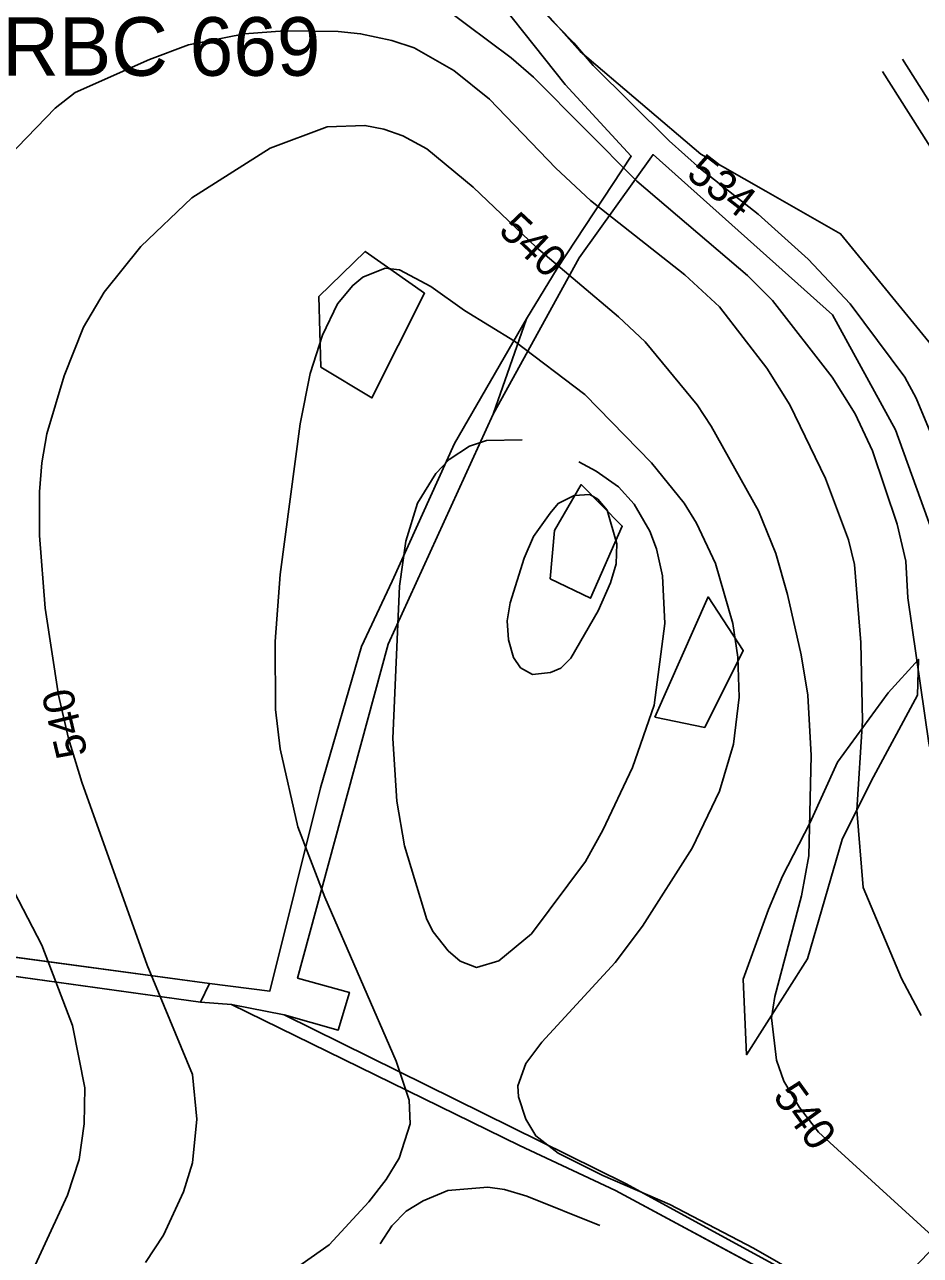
# Model space of a CAD drawing. Extents: x -709418 to -703832, y -1161719 to -1157826.
# Drawn here: x -708387.9 to -708158.7, y -1158300.7 to -1157985.6 of the extents above; entities that cross this region are included whole.
import ezdxf

# ---------------------------------------------------------------- set-up
doc = ezdxf.new("R2010")
doc.units = 0
for name, color, linetype in [('102_obvod PÚ', 7, 'Continuous'), ('103_hranice KÚ', 7, 'Continuous'), ('120_vrstevnice hlavní', 7, 'Continuous'), ('121_vrstevnice hlavní_popis', 7, 'Continuous'), ('122_vrstevnice základní', 7, 'Continuous'), ('124_vrstevnice doplňková', 7, 'Continuous'), ('206_TTP_KN', 7, 'Continuous'), ('210_ostatní plocha_KN', 7, 'Continuous'), ('501_vodní tok', 7, 'Continuous'), ('605_RBC_návrh_popis', 7, 'Continuous'), ('735_OP sítí TI', 7, 'Continuous')]:
    doc.layers.add(name, color=color, linetype=linetype)

msp = doc.modelspace()

# ---------------------------------------------------------------- linework, layer by layer
at = {"layer": '102_obvod PÚ'}
msp.add_lwpolyline([(-708273.66, -1157970.5), (-708249.53, -1158000.91), (-708232.65, -1158019.27), (-708251.62, -1158048.01), (-708259.43, -1158060.9), (-708267.99, -1158085.37), (-708245.93, -1158045.28), (-708227.05, -1158018.9), (-708181.16, -1158059.93), (-708164.98, -1158089.32), (-708147.17, -1158138.79)], dxfattribs=at)
at = {"layer": '103_hranice KÚ'}
msp.add_lwpolyline([(-708154.2, -1158069.65), (-708179.06, -1158039.17), (-708198.21, -1158028.27), (-708214.82, -1158018.74), (-708245.71, -1157992.5), (-708254.08, -1157983.08)], dxfattribs=at)
at = {"layer": '120_vrstevnice hlavní'}
for points in [[(-708195.48, -1158250.69), (-708196.76, -1158239.84), (-708195.91, -1158234.41), (-708189.05, -1158208.69), (-708187.19, -1158198.41), (-708186.62, -1158172.69), (-708187.48, -1158157.26), (-708189.19, -1158146.97), (-708192.62, -1158131.55), (-708195.62, -1158120.97), (-708200.05, -1158110.11), (-708212.19, -1158088.4), (-708215.76, -1158082.97), (-708229.05, -1158066.83), (-708235.91, -1158060.4), (-708256.91, -1158042.68), (-708273.05, -1158027.25), (-708284.91, -1158017.4), (-708291.05, -1158014.11), (-708295.91, -1158012.4), (-708300.77, -1158011.4), (-708310.48, -1158011.82), (-708325.06, -1158017.25), (-708345.06, -1158029.97), (-708358.11, -1158042.45), (-708367.48, -1158054.11), (-708372.77, -1158063.11), (-708377.77, -1158075.54), (-708382.2, -1158090.4), (-708383.49, -1158097.83), (-708384.06, -1158105.26), (-708384.06, -1158116.4), (-708382.63, -1158134.97), (-708379.2, -1158157.26), (-708376.63, -1158168.4), (-708373.2, -1158179.55), (-708356.48, -1158226.41), (-708344.91, -1158254.41), (-708343.77, -1158265.84), (-708344.91, -1158276.98), (-708347.2, -1158284.41), (-708352.34, -1158295.55), (-708356.91, -1158302.55)], [(-708133.62, -1158318.41), (-708155.62, -1158295.7), (-708184.76, -1158269.12), (-708189.62, -1158262.84), (-708193.62, -1158256.12), (-708195.48, -1158250.69)]]:
    msp.add_lwpolyline(points, dxfattribs=at)
at = {"layer": '122_vrstevnice základní'}
for points in [[(-708266.91, -1157970.11), (-708247.34, -1157990.25), (-708242.34, -1157996.11), (-708222.91, -1158015.4), (-708214.91, -1158022.54), (-708200.19, -1158034.11), (-708187.33, -1158045.68), (-708176.62, -1158057.11), (-708162.62, -1158075.83), (-708159.76, -1158081.26), (-708151.9, -1158100.11), (-708147.33, -1158116.11), (-708141.05, -1158148.4), (-708132.05, -1158173.55), (-708125.62, -1158187.26), (-708121.76, -1158194.12), (-708114.33, -1158203.55), (-708096.04, -1158222.98), (-708081.9, -1158235.12), (-708069.9, -1158243.12), (-708045.9, -1158254.98), (-708033.9, -1158261.84), (-708019.61, -1158271.41), (-708005.61, -1158282.55)], [(-708286.2, -1157976.97), (-708263.34, -1157994.11), (-708257.62, -1157999.11), (-708231.19, -1158025.68), (-708202.91, -1158049.83), (-708196.48, -1158056.26), (-708181.19, -1158075.83), (-708175.33, -1158085.26), (-708170.9, -1158094.69), (-708164.62, -1158113.54), (-708162.33, -1158122.97), (-708161.9, -1158132.4), (-708156.47, -1158169.55), (-708151.33, -1158193.55), (-708149.47, -1158196.98), (-708138.05, -1158220.98), (-708127.76, -1158238.12), (-708119.33, -1158250.69), (-708111.9, -1158260.12), (-708099.61, -1158272.69), (-708088.47, -1158285.27), (-708079.9, -1158297.84), (-708067.47, -1158319.84)], [(-708158.47, -1158239.26), (-708163.47, -1158229.83), (-708173.33, -1158206.55), (-708174.91, -1158186.69), (-708173.48, -1158163.83), (-708173.91, -1158143.83), (-708175.48, -1158123.83), (-708177.05, -1158117.54), (-708182.91, -1158101.83), (-708192.05, -1158082.97), (-708197.91, -1158073.54), (-708210.05, -1158057.83), (-708218.91, -1158049.68), (-708243.05, -1158030.68), (-708251.91, -1158022.4), (-708268.91, -1158004.68), (-708278.05, -1157997.4), (-708288.2, -1157991.54), (-708293.91, -1157989.68), (-708301.91, -1157987.97), (-708307.62, -1157987.39), (-708321.34, -1157987.25), (-708331.63, -1157987.97), (-708345.91, -1157990.82), (-708355.91, -1157994.54), (-708374.91, -1158002.97), (-708380.06, -1158006.97), (-708399.42, -1158026.97)], [(-708329.77, -1158311.98), (-708309.91, -1158297.98), (-708299.77, -1158286.98), (-708295.34, -1158281.27), (-708292.05, -1158275.84), (-708289.2, -1158266.98), (-708289.48, -1158260.98), (-708292.77, -1158250.98), (-708311.05, -1158208.98), (-708317.91, -1158190.98), (-708322.48, -1158170.98), (-708323.63, -1158160.98), (-708323.77, -1158143.55), (-708322.48, -1158126.4), (-708317.34, -1158087.83), (-708314.77, -1158074.97), (-708311.62, -1158065.11), (-708307.77, -1158057.11), (-708303.91, -1158052.4), (-708301.34, -1158050.26), (-708295.62, -1158047.97), (-708291.91, -1158048.4), (-708283.91, -1158052.68), (-708275.34, -1158058.83), (-708262.48, -1158066.68), (-708244.48, -1158080.27), (-708227.48, -1158097.83), (-708219.05, -1158108.11), (-708215.91, -1158113.26), (-708211.05, -1158123.54), (-708206.62, -1158138.97), (-708205.33, -1158147.55)], [(-708241.07, -1158135.65), (-708237.93, -1158128.51), (-708236.5, -1158123.65), (-708236.35, -1158118.51), (-708238.78, -1158109.94), (-708241.21, -1158107.08), (-708243.21, -1158105.94), (-708247.21, -1158106.19), (-708251.36, -1158108.21), (-708253.35, -1158110.65), (-708257.64, -1158116.65), (-708260.07, -1158122.22), (-708263.64, -1158133.65), (-708264.35, -1158138.22), (-708264.07, -1158143.08), (-708262.78, -1158147.65), (-708260.94, -1158150.3), (-708257.87, -1158152.01), (-708253.26, -1158151.49), (-708250.64, -1158150.37), (-708248.07, -1158147.8), (-708241.07, -1158135.65)], [(-708205.33, -1158147.55), (-708205.05, -1158157.83), (-708206.48, -1158169.83), (-708210.05, -1158181.83), (-708217.05, -1158196.41), (-708229.76, -1158216.41), (-708236.76, -1158225.69), (-708255.48, -1158246.12), (-708259.62, -1158251.55), (-708261.62, -1158257.27), (-708261.48, -1158260.12), (-708259.62, -1158265.84), (-708257.05, -1158270.12), (-708251.34, -1158274.55), (-708239.91, -1158280.27), (-708222.76, -1158287.7), (-708201.34, -1158298.84), (-708182.76, -1158309.55)], [(-708396.63, -1158196.12), (-708383.49, -1158221.26), (-708375.63, -1158241.84), (-708372.48, -1158257.84), (-708372.63, -1158266.98), (-708373.91, -1158276.12), (-708376.91, -1158285.27), (-708405.49, -1158346.98)]]:
    msp.add_lwpolyline(points, dxfattribs=at)
at = {"layer": '124_vrstevnice doplňková'}
for points in [[(-708260.57, -1158091.94), (-708269.69, -1158092.07), (-708274.04, -1158093.57), (-708279.2, -1158096.97), (-708282.62, -1158100.54), (-708287.34, -1158108.11), (-708290.34, -1158117.83), (-708291.91, -1158129.4), (-708293.62, -1158168.4), (-708292.62, -1158184.4), (-708290.62, -1158195.83), (-708284.91, -1158214.69), (-708283.34, -1158217.83), (-708279.48, -1158222.69), (-708276.44, -1158225.34), (-708272.21, -1158226.96), (-708266.48, -1158225.26), (-708258.19, -1158218.41), (-708244.34, -1158199.83), (-708239.91, -1158191.83), (-708232.34, -1158175.83), (-708226.76, -1158159.83), (-708224.05, -1158138.97), (-708224.62, -1158126.69), (-708226.19, -1158119.83), (-708227.91, -1158115.26), (-708231.91, -1158108.4), (-708235.91, -1158103.97), (-708241.62, -1158099.97), (-708246.05, -1158097.54)], [(-708240.63, -1158293.08), (-708259.34, -1158285.55), (-708265.05, -1158283.84), (-708269.34, -1158283.27), (-708279.53, -1158284.11), (-708285.91, -1158286.69), (-708290.2, -1158289.41), (-708293.91, -1158293.12), (-708296.91, -1158297.7)]]:
    msp.add_lwpolyline(points, dxfattribs=at)
at = {"layer": '206_TTP_KN'}
for p, q in [((-708166.91, -1158156.7), (-708159.13, -1158148.13)), ((-708159.13, -1158148.13), (-708159.35, -1158157.27)), ((-708179.83, -1158174.39), (-708166.91, -1158156.7)), ((-708159.35, -1158157.27), (-708171.26, -1158179.32)), ((-708186.96, -1158190.02), (-708179.83, -1158174.39)), ((-708171.26, -1158179.32), (-708178.69, -1158194.23)), ((-708193.89, -1158203.65), (-708186.96, -1158190.02)), ((-708178.69, -1158194.23), (-708187.53, -1158224.77)), ((-708197.52, -1158212.14), (-708193.89, -1158203.65)), ((-708204.02, -1158229.98), (-708197.52, -1158212.14)), ((-708450.77, -1158216.2), (-708340.52, -1158231.09)), ((-708342.87, -1158235.88), (-708449.83, -1158221.04)), ((-708187.53, -1158224.77), (-708203.16, -1158249.32)), ((-708203.16, -1158249.32), (-708204.02, -1158229.98)), ((-708340.52, -1158231.09), (-708342.87, -1158235.88))]:
    msp.add_line(p, q, dxfattribs=at)
for points in [[(-708407.64, -1157938.73), (-708381.35, -1157943.7), (-708320.38, -1157935.37), (-708307.31, -1157939.65), (-708307.88, -1157944.67), (-708293.34, -1157952.82), (-708273.66, -1157970.5), (-708249.53, -1158000.91), (-708232.65, -1158019.27), (-708251.62, -1158048.01), (-708259.43, -1158060.9), (-708277.82, -1158092.81), (-708293.81, -1158128.1), (-708301.62, -1158144.83), (-708312.16, -1158181.02), (-708325.11, -1158233.02), (-708340.52, -1158231.09), (-708450.77, -1158216.2)], [(-708321.46, -1158239.09), (-708307.61, -1158243.01), (-708304.76, -1158233.38), (-708318.03, -1158229.74), (-708305.33, -1158182.86), (-708294.86, -1158144.25), (-708267.99, -1158085.37), (-708245.93, -1158045.28), (-708227.05, -1158018.9), (-708181.16, -1158059.93), (-708164.98, -1158089.32), (-708147.17, -1158138.79), (-708150.07, -1158141.93), (-708137.6, -1158183.55), (-708122.95, -1158215.39), (-708106.77, -1158247.98), (-708171.98, -1158316.17), (-708234.11, -1158282.26), (-708321.46, -1158239.09)], [(-708312.56, -1158055.22), (-708312.06, -1158073.28), (-708299, -1158081.2), (-708285.51, -1158054.37), (-708300.71, -1158043.66), (-708312.56, -1158055.22)], [(-708253.4, -1158127.48), (-708243.05, -1158132.47), (-708234.92, -1158113.99), (-708245.41, -1158103.36), (-708252.26, -1158115.13), (-708253.4, -1158127.48)], [(-708226.62, -1158162.89), (-708213.81, -1158165.53), (-708203.96, -1158145.87), (-708212.99, -1158132.13), (-708226.62, -1158162.89)], [(-708204.02, -1158229.98), (-708203.16, -1158249.32), (-708187.53, -1158224.77), (-708178.69, -1158194.23), (-708171.26, -1158179.32), (-708159.35, -1158157.27), (-708159.13, -1158148.13), (-708166.91, -1158156.7), (-708179.83, -1158174.39), (-708186.96, -1158190.02), (-708193.89, -1158203.65), (-708197.52, -1158212.14), (-708204.02, -1158229.98)], [(-708451.04, -1158328.33), (-708444.59, -1158289.87), (-708444.09, -1158258.83), (-708449.83, -1158221.04), (-708342.87, -1158235.88), (-708334.95, -1158236.45), (-708261.23, -1158272.55), (-708236.68, -1158284.11), (-708173.73, -1158317.92)]]:
    msp.add_lwpolyline(points, dxfattribs=at)
at = {"layer": '210_ostatní plocha_KN'}
for p, q in [((-708312.56, -1158055.22), (-708300.71, -1158043.66)), ((-708300.71, -1158043.66), (-708285.51, -1158054.37)), ((-708312.06, -1158073.28), (-708312.56, -1158055.22)), ((-708285.51, -1158054.37), (-708299, -1158081.2)), ((-708277.82, -1158092.81), (-708259.43, -1158060.9)), ((-708259.43, -1158060.9), (-708267.99, -1158085.37)), ((-708299, -1158081.2), (-708312.06, -1158073.28)), ((-708267.99, -1158085.37), (-708294.86, -1158144.25)), ((-708293.81, -1158128.1), (-708277.82, -1158092.81)), ((-708252.26, -1158115.13), (-708245.41, -1158103.36)), ((-708245.41, -1158103.36), (-708234.92, -1158113.99)), ((-708253.4, -1158127.48), (-708252.26, -1158115.13)), ((-708234.92, -1158113.99), (-708243.05, -1158132.47)), ((-708301.62, -1158144.83), (-708293.81, -1158128.1)), ((-708243.05, -1158132.47), (-708253.4, -1158127.48)), ((-708226.62, -1158162.89), (-708212.99, -1158132.13)), ((-708212.99, -1158132.13), (-708203.96, -1158145.87)), ((-708312.16, -1158181.02), (-708301.62, -1158144.83)), ((-708294.86, -1158144.25), (-708305.33, -1158182.86)), ((-708203.96, -1158145.87), (-708213.81, -1158165.53)), ((-708213.81, -1158165.53), (-708226.62, -1158162.89)), ((-708325.11, -1158233.02), (-708312.16, -1158181.02)), ((-708305.33, -1158182.86), (-708318.03, -1158229.74)), ((-708318.03, -1158229.74), (-708304.76, -1158233.38)), ((-708342.87, -1158235.88), (-708340.52, -1158231.09)), ((-708340.52, -1158231.09), (-708325.11, -1158233.02)), ((-708334.95, -1158236.45), (-708342.87, -1158235.88)), ((-708304.76, -1158233.38), (-708307.61, -1158243.01)), ((-708334.95, -1158236.45), (-708321.46, -1158239.09)), ((-708261.23, -1158272.55), (-708334.95, -1158236.45)), ((-708321.46, -1158239.09), (-708334.95, -1158236.45)), ((-708321.46, -1158239.09), (-708234.11, -1158282.26)), ((-708307.61, -1158243.01), (-708321.46, -1158239.09)), ((-708236.68, -1158284.11), (-708261.23, -1158272.55)), ((-708234.11, -1158282.26), (-708171.98, -1158316.17)), ((-708173.73, -1158317.92), (-708236.68, -1158284.11))]:
    msp.add_line(p, q, dxfattribs=at)
at = {"layer": '501_vodní tok'}
msp.add_lwpolyline([(-707952.7, -1158343.23), (-707960.11, -1158299.73), (-707965.84, -1158275.96), (-707970.24, -1158256.53), (-707973.1, -1158246.36), (-707986.26, -1158231.22), (-707992, -1158223.04), (-707999.69, -1158215.6), (-708010.93, -1158204.74), (-708030.71, -1158181.07), (-708058.47, -1158151.67), (-708073.54, -1158127.12), (-708093.22, -1158105.25), (-708115.76, -1158069.36), (-708163.24, -1157994.43)], dxfattribs=at)
at = {"layer": '735_OP sítí TI'}
msp.add_lwpolyline([(-708122.19, -1158070.43), (-708168.31, -1157997.64)], dxfattribs=at)

# ---------------------------------------------------------------- texts
at = {"layer": '121_vrstevnice hlavní_popis'}
for s, rotation, p in [('534', 322.2355, (-708218.88, -1158024.52)), ('540', 316.8453, (-708266.93, -1158038.72)), ('540', 103.4898, (-708371.67, -1158172.35)), ('540', 305.852, (-708196.6, -1158259.96))]:
    msp.add_text(s, height=8, rotation=rotation, dxfattribs=at).set_placement(p)
at = {"layer": '605_RBC_návrh_popis'}
msp.add_text('RBC 669', height=15, dxfattribs=at).set_placement((-708393.55, -1157998.71))

doc.saveas('drawing.dxf')
